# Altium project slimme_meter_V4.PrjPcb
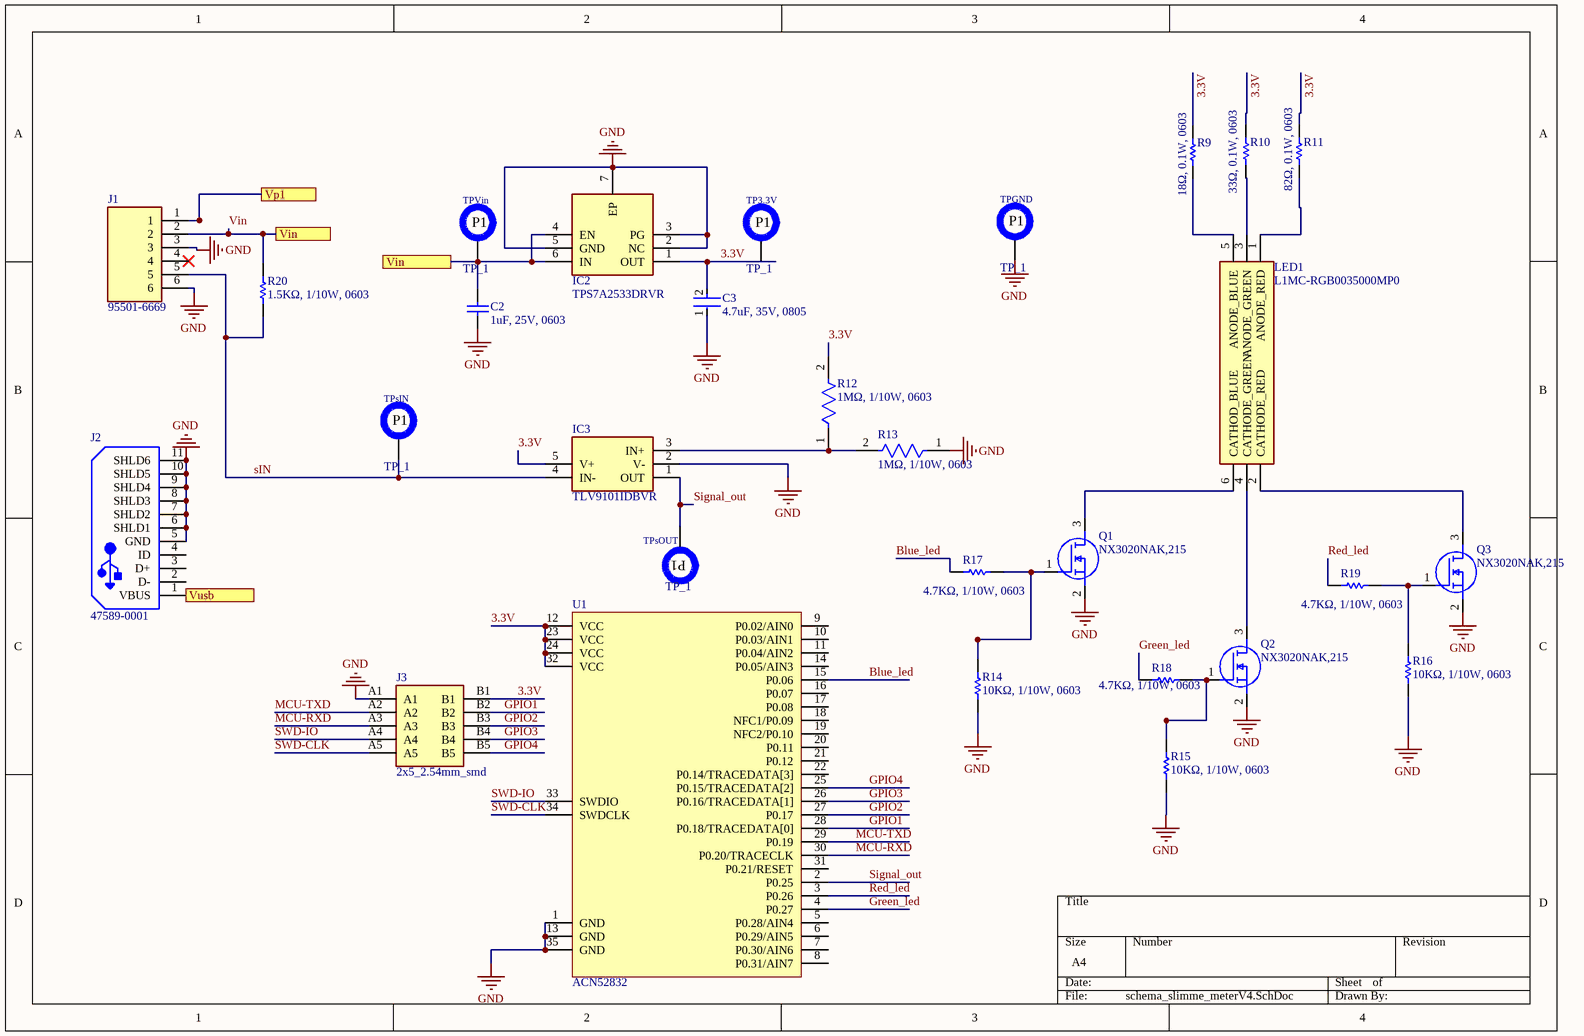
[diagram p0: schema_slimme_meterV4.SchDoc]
2 sheets, 37 parts. Net scope: flat (ports and power ports of the same name join across sheets).
Board file: PCB_slimme_meterV2.PcbDoc
Sheets:
  schema_slimme_meterV4.SchDoc
  Spanningsbronschakelaar.SchDoc

## Sheet schema_slimme_meterV4.SchDoc
size A4; SheetNumber: 1; SheetTotal: 2

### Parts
C2  1uF, 25V, 0603  [CAPC1608X90X35LL10T15]
C3  4.7uF, 35V, 0805  [FP-GRM219-0_15-0_1-IPC_B]
IC2  TPS7A2533DRVR  [SON65P200X200X80-7N]
IC3  TLV9101IDBVR  [SOT95P280X145-5N]
J1  95501-6669  [95501-6669]
J2  47589-0001  [MOLX-47589-0001_V]
J3  2x5_2.54mm_smd  [10129383910001ALF]
LED1  L1MC-RGB0035000MP0  [L1MCRGB0035000MP0]
Q1  NX3020NAK,215  [SOT95P230X110-3N]
Q2  NX3020NAK,215  [SOT95P230X110-3N]
Q3  NX3020NAK,215  [SOT95P230X110-3N]
R9  18Ω, 0.1W, 0603  [RESC1608X55X30ML15T15]
R10  33Ω, 0.1W, 0603  [RESC1608X55X30ML15T15]
R11  82Ω, 0.1W, 0603  [RESC1608X55X30LL15T15]
R12  1MΩ, 1/10W, 0603  [FP-CRCW0603-e3-IPC_B]
R13  1MΩ, 1/10W, 0603  [FP-CRCW0603-e3-IPC_B]
R14  10KΩ, 1/10W, 0603  [RESC1609X50X30NL8T20]
R15  10KΩ, 1/10W, 0603  [RESC1609X50X30NL8T20]
R16  10KΩ, 1/10W, 0603  [RESC1609X50X30NL8T20]
R17  4.7KΩ, 1/10W, 0603  [RESC1608X55X30NL15T15]
R18  4.7KΩ, 1/10W, 0603  [RESC1608X55X30NL15T15]
R19  4.7KΩ, 1/10W, 0603  [RESC1608X55X30NL15T15]
R20  1.5KΩ, 1/10W, 0603  [RESC1608X55X30ML15T15]
TP3.3V  TP_1  [PCBComponent_1]  (no BOM)
TPGND  TP_1  [PCBComponent_1]  (no BOM)
TPsIN  TP_1  [PCBComponent_1]  (no BOM)
TPsOUT  TP_1  [PCBComponent_1]  (no BOM)
TPVin  TP_1  [PCBComponent_1]  (no BOM)
U1  ACN52832  [ACN52832]  (no BOM)

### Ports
Vin, Vp1, Vusb

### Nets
GND: C2.1 C3.1 IC2.2(NC) IC2.3(PG) IC2.5(GND) IC2.7(EP) IC3.2(V-) J1.3 J1.6 J2.5(GND) J2.6(SHLD1) J2.7(SHLD2) J2.8(SHLD3) J2.9(SHLD4) J2.10(SHLD5) J2.11(SHLD6) J3.A1 Q1.2(S) Q2.2(S) Q3.2(S) R13.1 R14.1 R15.1 R16.1 U1.1(GND) U1.13(GND) U1.35(GND)
3.3V: C3.2 IC2.1(OUT) IC3.5(V+) J3.B1 R9.2 R10.2 R11.2 R12.2 U1.12(VCC) U1.23(VCC) U1.24(VCC) U1.32(VCC)
Blue_led: R17.1 U1.15(P0.06)
GPIO1: J3.B2 U1.28(P0.18/TRACEDATA[0])
GPIO2: J3.B3 U1.27(P0.17)
GPIO3: J3.B4 U1.26(P0.16/TRACEDATA[1])
GPIO4: J3.B5 U1.25(P0.15/TRACEDATA[2])
Green_led: R18.1 U1.4(P0.27)
MCU-RXD: J3.A3 U1.30(P0.20/TRACECLK)
MCU-TXD: J3.A2 U1.29(P0.19)
Red_led: R19.1 U1.3(P0.26)
Signal_out: IC3.1(OUT) U1.2(P0.25)
sIN: IC3.4(IN-) J1.5 R20.1
SWD-CLK: J3.A5 U1.34(SWDCLK)
SWD-IO: J3.A4 U1.33(SWDIO)
Vin: C2.2 IC2.4(EN) IC2.6(IN) J1.2 R20.2 ; port Vin
NetD1_2: J2.1(VBUS) ; port Vusb
NetIC3_3: IC3.3(IN+) R12.1 R13.2
NetJ1_1: J1.1 ; port Vp1
NetLED1_1: LED1.1(ANODE_RED) R11.1
NetLED1_2: LED1.2(CATHODE_RED) Q3.3(D)
NetLED1_3: LED1.3(ANODE_GREEN) R10.1
NetLED1_4: LED1.4(CATHODE_GREEN) Q2.3(D)
NetLED1_5: LED1.5(ANODE_BLUE) R9.1
NetLED1_6: LED1.6(CATHOD_BLUE) Q1.3(D)
NetQ1_1: Q1.1(G) R14.2 R17.2
NetQ2_1: Q2.1(G) R15.2 R18.2
NetQ3_1: Q3.1(G) R16.2 R19.2

Not connected (* = marked no-connect by the designer): J1 4*; J2 2(D-) 3(D+) 4(ID); U1 5(P0.28/AIN4) 6(P0.29/AIN5) 7(P0.30/AIN6) 8(P0.31/AIN7) 9(P0.02/AIN0) 10(P0.03/AIN1) 11(P0.04/AIN2) 14(P0.05/AIN3) 16(P0.07) 17(P0.08) 18(NFC1/P0.09) 19(NFC2/P0.10) 20(P0.11) 21(P0.12) 22(P0.14/TRACEDATA[3]) 31(P0.21/RESET)

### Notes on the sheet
- Labels drawn without touching a wire or pin: GND

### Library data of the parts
C2 = CMP-2006-02459-1: Manufacturer: Murata; Part Number: GRM188R61E105KA12D
C3 = CMP-06035-049019-1: Chip Multilayer Ceramic Capacitors for General Purpose, 0805, 4.7uF, X5R, 15%, 10%, 35V
IC2 = TPS7A2533DRVR: Integrated Circuit; Manufacturer_Name: Texas Instruments
IC3 = TLV9101IDBVR: Integrated Circuit; Manufacturer_Name: Texas Instruments
J1 = 95501-6669: Connector; Manufacturer_Name: Molex
J2 = CMP-2000-05610-1: Right Angle Female Type AB Micro USB Connector, 30 V, 1.8 A, -30 to 85 degC, RoHS, Tape and Reel; Number of Ports: 1Port; Current Rating: 1.8A; Brand: Molex; Connector Type: MicroUSBTypeABreceptacle; Number of Contacts: 5Contact; Voltage Rating: 30VAC
J3 = 2x5_2.54mm_smd: Connector; Manufacturer_Name: Amphenol; Manufacturer_Part_Number: 10129383-910001ALF
LED1 = L1MC-RGB0035000MP0: LED; Manufacturer_Name: Lumileds
Q1-Q3 = NX3020NAK,215: MOSFET (N-Channel); Manufacturer_Name: Nexperia
R9 = CMP-2000-00306-1: Part Number: ERJ3EKF18R0V; Manufacturer: Panasonic
R10 = CMP-2000-00443-1: Part Number: ERJ3EKF33R0V; Manufacturer: Panasonic
R11 = CMP-2000-00662-1: Part Number: ERJ3EKF82R0V; Manufacturer: Panasonic
R12 R13 = CMP-2000-03016-2: RES Thick Film, 1MΩ, 5%, 0.1W, 200ppm/°C, 0603; Max Power Dissipation: 100mW; Resistance: 1MR; Voltage Rating: 75V
R14-R16 = CMP-1666-00005-4: Chip Resistor, 10 KOhm, +/- 1%, 100 mW, -55 to 155 degC, 0603 (1608 Metric), RoHS, Tape and Reel; Manufacturer: Vishay Semiconductor; Voltage Rating: 75 V
R17-R19 = CMP-1012-00586-3: Precision Thick Film Chip Resistor, 4.7 KOhm, +/- 1%, -55 to 155 degC, 0603 (1608 Metric), RoHS, Tape and Reel; Resistance: 220 Ohm; Voltage Rating: 50 V; Elements: 4; Case\Package: 1205; Tolerance: 5%; Power Rating: 250 mW
R20 = CMP-1012-00528-2: Part Number: ERJ-3EKF1501V; Manufacturer: Panasonic
TP3.3V TPGND TPsIN TPsOUT TPVin = TestPoint
U1 = ACN52832: Bluetooth-Module (802.15.1) Bluetooth Low Energy Smart Module

## Sheet Spanningsbronschakelaar.SchDoc
size A4; SheetNumber: 2; SheetTotal: 2; SPICEModelCacheZYFRAJNV: <root> / <DocumentId>ZYFRAJNV</DocumentId> / <CacheFrame Number="0"> / <Model Name="diode" Kind="MDL"> / <Text>.MODEL diode D ()</Text> / </Model> / <Model Name="nmosfet_level3" Kind="MDL"> / <Text>*------------ / *MOS3 / .model NMOSFET_Level3 nmos (Level=3) </Text> / </Model> / <Model Name="pmos_ssm6p36tu" Kind="CKT"> / <Text>********************************************************************* / *  (C)  Copyright  TOSHIBA CORPORATION  2016 / *  Date                 : 04/08/2016 / *  File Name            : SSM6P36TU.lib / *  Part Number          : SSM6P36TU / *  Parameter Ver.       : Ver.1 / *  Simulator            : PSpice / *  Model Call Name      : PMOS_SSM6P36TU / *  TNOM                 : 25 degree / *  Pin Assign           : 1=Drain 2=Gate 3=Source / * / * Operation of this model has been verified only on the OrCAD. / ********************************************************************* / .SUBCKT PMOS_SSM6P36TU 1 2 3 / M0 1 22 3 3 smsmosfet / + L = 5e-06 / + W = 0.006 / + AD = 6e-09 / + AS = 6e-09 / + PD = 0.012 / + PS = 0.012 / D0 1 3 DDS1 / D1 1 3 DDS2 / D2 10 2 DGS1 / D3 10 3 DGS2 / R2 10 2 1E+009 / R3 10 3 1E+009 / RG 2 22 900 / .MODEL smsmosfet PMOS / + LEVEL = 7 / + MOBMOD = 1 / + CAPMOD = 3 / + NOIMOD = 1 / + TOX = 1.5e-08 / + XJ = 1.5E-007 / + NCH = 1.7E+017 / + NGATE = 0 / + RSH = 0 / + TNOM = 25 / + VTH0 = -0.625 / + VOFF = -0.08 / + NFACTOR = 1.8 / + U0 = 3708.0942 / + K1 = 0.5 / + K2 = 0 / + K3 = 80 / + K3B = 0 / + W0 = 2.5E-006 / + NLX = 1.74E-007 / + DVT0 = 2.2 / + DVT1 = 0.53 / + DVT2 = -0.032 / + DVT0W = 0 / + DVT1W = 5.3E+006 / + DVT2W = -0.032 / + DWG = 0 / + DWB = 0 / + UA = 2.8397e-09 / + UB = 5.87E-019 / + UC = -4.65E-011 / + VSAT = 78492.4499 / + A0 = 0.39234 / + AGS = 4.0924 / + B0 = 0 / + B1 = 0 / + KETA = -0.047 / + A1 = 0 / + A2 = 1 / + DELTA = 0.0072514 / + RDSW = 2900 / + PRWG = 0 / + PRWB = 0 / + WR = 1 / + CDSC = 2.4E-004 / + CDSCD = 0 / + CDSCB = 0 / + CIT = 0 / + ETA0 = 0.08 / + ETAB = -0.07 / + DSUB = 0.56 / + PCLM = 19.9147 / + PDIBLC1 = 0.39 / + PDIBLC2 = 0.0017779 / + PDIBLCB = 0 / + DROUT = 0.56 / + PSCBE1 = 4.24E+008 / + PSCBE2 = 1E-009 / + PVAG = 0 / + ALPHA0 = 0 / + ALPHA1 = 0 / + BETA0 = 30 / + NJ = 1 / + JS = 0 / + XPART = 0 / + CGSO = 1.5331e-08 / + CGDO = 9.599e-11 / + CGBO = 0 / + CGDL = 1.86e-08 / + CGSL = 2.6803e-10 / + CKAPPA = 2.637 / + CF = 0 / + CLC = 1E-007 / + CLE = 0.6 / + VOFFCV = 0 / + NOFF = 1 / + DLC = 0 / + ACDE = 1 / + MOIN = 15 / + CJ = 0 / + CJSW = 1E-012 / + CJSWG = 1E-012 / + PB = 1 / + PBSW = 1 / + PBSWG = 1 / + MJ = 0.5 / + MJSW = 0.33 / + MJSWG = 0.33 / + AF = 1 / + EF = 1 / + KF = 0 / + UTE = -1.78 / + KT1 = -0.52 / + KT1L = 0 / + KT2 = 0.022 / + UA1 = 4.31E-009 / + UB1 = -7.61E-018 / + UC1 = -5.6E-011 / + AT = 3300 / + PRT = 1000 / + XTI = 3 / + TCJ = 0 / + TPB = 0 / + TCJSW = 0 / + TPBSW = 0 / + TCJSWG = 0 / + TPBSWG = 0 / + DWC = 0.00019 / .MODEL DDS1 D / + TNOM = 25 / + IS = 3.2524e-18 / + RS = 0.72522 / + N = 0.80002 / + CJO = 1e-12 / + VJ = 0.9 / + M = 0.6 / + XTI = 3 / + BV = 20 / + IBV = 0.001 / .MODEL DDS2 D / + TNOM = 25 / + IS = 3.2524e-18 / + RS = 0.72522 / + N = 0.80002 / + CJO = 1e-15 / + VJ = 0.7 / + M = 0.3 / + XTI = 3 / .MODEL DGS1 D / + TNOM = 25 / + IS = 1E-015 / .MODEL DGS2 D / + TNOM = 25 / + IS = 1E-015 / .ENDS</Text> / </Model> / </CacheFrame> / </root>
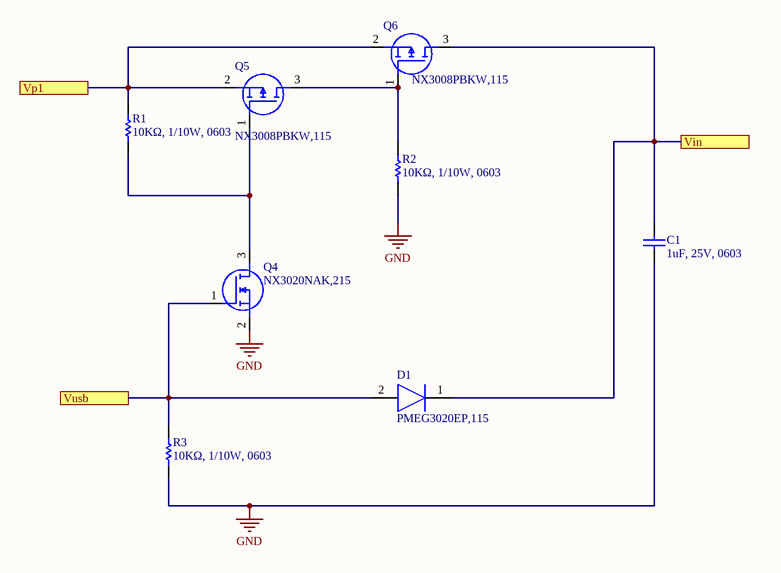
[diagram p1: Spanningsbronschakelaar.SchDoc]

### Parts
C1  1uF, 25V, 0603  [CAPC1608X90X35LL10T15]
D1  PMEG3020EP,115  [SODFL4725X110N]
Q4  NX3020NAK,215  [SOT95P230X110-3N]
Q5  NX3008PBKW,115  [SOT65P210X110-3N]
Q6  NX3008PBKW,115  [SOT65P210X110-3N]
R1  10KΩ, 1/10W, 0603  [RESC1609X50X30NL8T20]
R2  10KΩ, 1/10W, 0603  [RESC1609X50X30NL8T20]
R3  10KΩ, 1/10W, 0603  [RESC1609X50X30NL8T20]

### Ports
Vin, Vp1, Vusb

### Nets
GND: C1.1 Q4.2(S) R2.1 R3.1
Vin: C1.2 D1.1(K) Q6.3(D) ; port Vin
NetD1_2: D1.2(A) Q4.1(G) R3.2 ; port Vusb
NetJ1_1: Q5.2(S) Q6.2(S) R1.2 ; port Vp1
NetQ4_3: Q4.3(D) Q5.1(G) R1.1
NetQ5_3: Q5.3(D) Q6.1(G) R2.2

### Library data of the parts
C1 = CMP-2006-02459-1: as C2 on sheet schema_slimme_meterV4
D1 = PMEG3020EP,115: Diode; Manufacturer_Name: Nexperia
Q4 = NX3020NAK,215: as Q1 on sheet schema_slimme_meterV4
Q5 Q6 = NX3008PBKW,115: MOSFET (P-Channel); Manufacturer_Name: Nexperia
R1-R3 = CMP-1666-00005-4: as R14 on sheet schema_slimme_meterV4

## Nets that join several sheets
GND: schema_slimme_meterV4 (27 pins), Spanningsbronschakelaar (C1.1 Q4.2 R2.1 R3.1)
NetD1_2: schema_slimme_meterV4 (J2.1), Spanningsbronschakelaar (D1.2 Q4.1 R3.2)
NetJ1_1: schema_slimme_meterV4 (J1.1), Spanningsbronschakelaar (Q5.2 Q6.2 R1.2)
Vin: schema_slimme_meterV4 (5 pins), Spanningsbronschakelaar (C1.2 D1.1 Q6.3)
